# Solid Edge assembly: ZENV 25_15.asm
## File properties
Title: Zylinder
Author: bmolnar
Template: iso metric assembly.asm
Last saved by: bmolnar
Revision: 11
Application: Solid Edge
Username: bmolnar
Dokumentum tartalom típus: 1
Document Number: ZENV 25/15
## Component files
Kit_1.par
Kit_2.par
Profilrohr.par
Kolbenstange.par
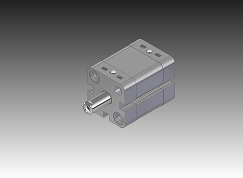
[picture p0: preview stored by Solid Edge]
